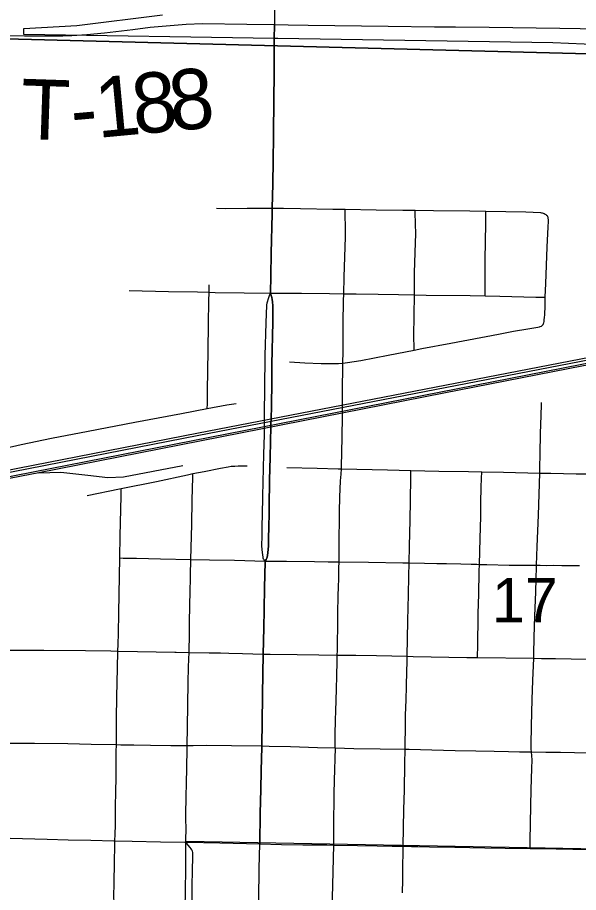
# Model space of a CAD drawing. Extents: x 0 to 34, y 0 to 22.
# Drawn here: x 6.731 to 7.261, y 17.768 to 18.594 of the extents above; entities that cross this region are included whole.
import ezdxf

# ---------------------------------------------------------------- set-up
doc = ezdxf.new("R2010")
doc.units = 0
for name, color, linetype in [('GM_X_City_Street', 7, 'Continuous'), ('GM_X_Corporation', 7, 'Continuous'), ('GM_X_County_Road', 7, 'Continuous'), ('GM_X_Rail_Line', 7, 'Continuous'), ('GM_X_Section_Text', 7, 'Continuous'), ('GM_X_State_Route', 7, 'Continuous'), ('GM_X_Township_Road', 7, 'Continuous'), ('GM_X_Township_Road_Text', 7, 'Continuous'), ('GM_X_US_Route', 7, 'Continuous')]:
    doc.layers.add(name, color=color, linetype=linetype)

msp = doc.modelspace()

# ---------------------------------------------------------------- linework, layer by layer
at = {"layer": 'GM_X_City_Street'}
for points in [[(6.91935, 18.41353), (6.92749, 18.41335), (6.94807, 18.41363), (6.97188, 18.41357)], [(6.97188, 18.41357), (6.97467, 18.41357), (6.98258, 18.41358), (6.99857, 18.41347), (7.02905, 18.41288), (7.04072, 18.41268), (7.0701, 18.4122), (7.09499, 18.41189), (7.10683, 18.41176), (7.12423, 18.41156), (7.15844, 18.4112), (7.17344, 18.41094), (7.21135, 18.4103), (7.22499, 18.40956), (7.2259, 18.4094), (7.22679, 18.40917), (7.2277, 18.40887), (7.22855, 18.40853), (7.2294, 18.40806), (7.23014, 18.40756), (7.23088, 18.40699), (7.23153, 18.40632)], [(7.03117, 17.90465), (7.03141, 17.9182), (7.03168, 17.92982), (7.0319, 17.94059), (7.03212, 17.94843), (7.03256, 17.96109), (7.03286, 17.97126), (7.033, 17.97692), (7.03315, 17.98159), (7.03322, 17.98709), (7.03329, 17.9922), (7.03339, 17.99637), (7.03342, 17.99986), (7.0335, 18.00472), (7.03358, 18.00969), (7.03365, 18.01332), (7.03368, 18.01959), (7.03372, 18.02643), (7.03371, 18.03208), (7.03378, 18.03728), (7.034, 18.04225), (7.03415, 18.04873), (7.03437, 18.05574), (7.03459, 18.06478), (7.03481, 18.07405), (7.03498, 18.08022), (7.03502, 18.08664), (7.03509, 18.09116), (7.03509, 18.0959), (7.03509, 18.10186), (7.03516, 18.10796), (7.03523, 18.11379), (7.0353, 18.11934), (7.03544, 18.12741), (7.03575, 18.1411), (7.0364, 18.15642), (7.03685, 18.16268), (7.03716, 18.16781), (7.03726, 18.16967), (7.03775, 18.19768), (7.03813, 18.21739), (7.03826, 18.22846), (7.03831, 18.23748), (7.03825, 18.24681), (7.03835, 18.26026), (7.03852, 18.26748), (7.03879, 18.27857), (7.03885, 18.28573), (7.0389, 18.29654), (7.03891, 18.30523), (7.0392, 18.32628), (7.03938, 18.33302), (7.03979, 18.34874), (7.04087, 18.38669), (7.04091, 18.39356), (7.04075, 18.40926), (7.04072, 18.41268)], [(7.10586, 18.27985), (7.10581, 18.28154), (7.10548, 18.29304), (7.10603, 18.33189), (7.10607, 18.34144), (7.10627, 18.35263), (7.10723, 18.3812), (7.1073, 18.38928), (7.10688, 18.40925), (7.10683, 18.41176)], [(7.17286, 18.33101), (7.17288, 18.33807), (7.17296, 18.36534), (7.17353, 18.39881), (7.17347, 18.40687), (7.17344, 18.41094)], [(7.22405, 18.3017), (7.22475, 18.30191), (7.22586, 18.30242), (7.22677, 18.30303), (7.22753, 18.30397), (7.22791, 18.30478), (7.22817, 18.30563), (7.22843, 18.30686), (7.22866, 18.30839), (7.22887, 18.31061), (7.22901, 18.31295), (7.22938, 18.32162), (7.22956, 18.32966), (7.22997, 18.34275), (7.23142, 18.37686), (7.23239, 18.39607), (7.23256, 18.40101), (7.2325, 18.4027), (7.23238, 18.4041), (7.23217, 18.40494), (7.23196, 18.40553), (7.23153, 18.40632)], [(6.9106, 18.22466), (6.91065, 18.22922), (6.91076, 18.24168), (6.91146, 18.27906), (6.91177, 18.30464), (6.91203, 18.3258), (6.91221, 18.33441), (6.91236, 18.34148)], [(6.83672, 18.33596), (6.87398, 18.3352), (6.90136, 18.33474), (6.91221, 18.33441), (6.91815, 18.33422), (6.94554, 18.33372), (6.97019, 18.33345)], [(6.97019, 18.33345), (6.98039, 18.33356), (6.99952, 18.33337), (7.02577, 18.33305), (7.03938, 18.33302), (7.05123, 18.333), (7.07171, 18.33253), (7.09096, 18.33217), (7.10603, 18.33189), (7.11703, 18.33168), (7.15864, 18.33129), (7.17286, 18.33101), (7.18657, 18.33074), (7.22071, 18.32988), (7.22956, 18.32966)], [(6.98822, 18.26859), (7.00266, 18.2679), (7.01816, 18.26725), (7.02804, 18.26706), (7.0344, 18.26721), (7.03852, 18.26748), (7.04302, 18.26797), (7.05563, 18.27004), (7.08123, 18.27503), (7.10586, 18.27985), (7.11294, 18.28123), (7.14035, 18.28641), (7.18552, 18.29487), (7.19956, 18.29759), (7.21305, 18.29994), (7.22246, 18.30141), (7.22405, 18.3017)], [(6.71977, 18.18742), (6.73483, 18.19074), (6.76344, 18.19674), (6.7983, 18.20334), (6.84229, 18.21188), (6.88634, 18.2201), (6.9106, 18.22466), (6.92916, 18.22815), (6.93772, 18.22953)], [(7.21658, 17.90088), (7.21624, 17.90352), (7.21615, 17.90743), (7.2166, 17.92534), (7.21727, 17.95015), (7.21778, 17.96812), (7.21863, 17.98909), (7.2188, 17.99377), (7.21904, 18.00848), (7.21937, 18.01929), (7.21971, 18.02873), (7.22059, 18.05182), (7.22092, 18.06416), (7.22096, 18.066), (7.22121, 18.07356), (7.22126, 18.07684), (7.22193, 18.09445), (7.22317, 18.1242), (7.22436, 18.16381), (7.22444, 18.16874), (7.22469, 18.1821), (7.2251, 18.20124), (7.22568, 18.21816), (7.2259, 18.22848), (7.22601, 18.2305)], [(6.79732, 18.14267), (6.82778, 18.14887), (6.8293, 18.14918), (6.8625, 18.15598), (6.89197, 18.16223), (6.89699, 18.16326), (6.90753, 18.16543), (6.9231, 18.16847), (6.93034, 18.1698), (6.93323, 18.17018), (6.93648, 18.17047), (6.93958, 18.17062), (6.94329, 18.1707), (6.94811, 18.17063)], [(6.98573, 18.16892), (7.01431, 18.16832), (7.0342, 18.16789), (7.03716, 18.16781), (7.0808, 18.16673), (7.10264, 18.16629), (7.12925, 18.16575), (7.15722, 18.16528), (7.16954, 18.16502), (7.19015, 18.16459), (7.22436, 18.16381), (7.2349, 18.16361), (7.25884, 18.16324), (7.27466, 18.163)], [(7.09551, 17.8118), (7.09618, 17.84643), (7.09661, 17.8648), (7.09703, 17.88962), (7.09721, 17.90335), (7.09753, 17.92815), (7.09777, 17.93559), (7.09823, 17.94984), (7.09855, 17.96263), (7.09888, 17.97743), (7.09913, 17.98525), (7.09929, 17.99112), (7.09986, 18.0243), (7.10011, 18.03705), (7.10044, 18.04905), (7.10093, 18.06657), (7.1011, 18.07899), (7.10134, 18.09473), (7.10197, 18.11932), (7.10233, 18.13786), (7.10257, 18.15957), (7.10264, 18.16629)], [(6.89161, 17.90672), (6.89185, 17.92416), (6.89265, 17.96632), (6.89291, 17.98087), (6.89313, 17.98818), (6.89335, 17.99466), (6.8937, 18.0126), (6.89393, 18.02375), (6.89422, 18.03784), (6.89453, 18.05351), (6.89462, 18.06341), (6.89488, 18.06959), (6.89512, 18.08011), (6.89518, 18.08223), (6.89589, 18.11539), (6.8964, 18.13829), (6.89691, 18.15992), (6.89699, 18.16326)], [(7.1656, 17.98984), (7.16563, 17.99173), (7.16578, 17.99977), (7.16593, 18.00672), (7.16605, 18.01174), (7.16615, 18.01858), (7.16623, 18.02287), (7.16638, 18.03067), (7.16661, 18.04113), (7.16676, 18.04909), (7.16728, 18.07141), (7.1674, 18.07767), (7.16814, 18.10217), (7.16868, 18.1227), (7.16865, 18.12636), (7.16872, 18.13018), (7.16879, 18.13588), (7.16902, 18.15063), (7.16932, 18.15859), (7.16954, 18.16502)], [(6.82337, 17.81688), (6.82357, 17.82334), (6.82385, 17.83176), (6.82385, 17.83787), (6.82388, 17.84449), (6.82398, 17.85315), (6.82413, 17.85927), (6.82435, 17.86665), (6.82457, 17.87336), (6.82457, 17.88165), (6.82464, 17.8864), (6.82471, 17.89355), (6.8247, 17.90082), (6.82475, 17.90769), (6.82477, 17.91111), (6.82492, 17.91714), (6.82491, 17.92204), (6.82491, 17.92619), (6.82498, 17.93229), (6.82526, 17.95279), (6.82568, 17.97993), (6.82621, 17.99597), (6.82643, 18.00252), (6.82665, 18.01247), (6.82707, 18.03208), (6.82807, 18.08371), (6.82845, 18.10475), (6.82916, 18.14201), (6.8293, 18.14918)], [(6.82807, 18.08371), (6.83127, 18.08366), (6.84371, 18.08343), (6.86641, 18.08291), (6.89518, 18.08223), (6.91272, 18.08196), (6.93629, 18.08159), (6.96507, 18.08087)], [(6.96507, 18.08087), (6.98537, 18.08083), (7.01168, 18.08041), (7.0246, 18.08018), (7.03498, 18.08022), (7.06265, 18.07983), (7.09498, 18.07909), (7.1011, 18.07899), (7.11573, 18.07872), (7.12719, 18.07858), (7.13637, 18.07846), (7.14975, 18.07816), (7.1595, 18.07789), (7.16507, 18.07774), (7.1674, 18.07767), (7.17061, 18.07757), (7.17431, 18.07748), (7.19537, 18.07708), (7.21094, 18.07696), (7.22126, 18.07684), (7.22482, 18.0768), (7.23077, 18.07673), (7.23733, 18.0768), (7.2452, 18.07674), (7.2528, 18.07667), (7.2618, 18.0766)], [(6.72045, 17.90906), (6.73489, 17.90918), (6.74754, 17.90908), (6.77907, 17.90877), (6.80094, 17.90823), (6.82475, 17.90769), (6.82902, 17.90759), (6.84123, 17.90738), (6.85711, 17.90706), (6.87631, 17.90674), (6.89161, 17.90672)], [(6.89593, 17.74841), (6.89636, 17.77391), (6.89673, 17.78943), (6.89692, 17.80126), (6.89696, 17.80495), (6.89683, 17.80606), (6.89655, 17.80718), (6.89604, 17.80839), (6.89538, 17.80946), (6.89447, 17.81063), (6.89256, 17.81291), (6.89027, 17.81555), (6.8903, 17.81734), (6.89049, 17.82874), (6.89048, 17.8372), (6.89046, 17.84365), (6.89075, 17.85661), (6.89104, 17.87342), (6.89115, 17.88315), (6.8916, 17.90621)], [(6.89161, 17.90672), (6.89729, 17.90687), (6.91017, 17.9071), (6.93341, 17.90695), (6.96194, 17.90641), (6.96911, 17.90626), (6.98921, 17.90583), (7.01474, 17.90507), (7.03117, 17.90465), (7.03037, 17.87375), (7.03009, 17.86146), (7.0298, 17.83019), (7.02973, 17.82387), (7.02961, 17.81294), (7.02781, 17.73798)], [(7.03117, 17.90465), (7.04901, 17.90415), (7.07381, 17.90376), (7.09721, 17.90335), (7.10116, 17.90328), (7.12242, 17.90272), (7.14466, 17.90222), (7.16394, 17.90176), (7.18137, 17.90143), (7.1948, 17.90111), (7.20534, 17.90101), (7.21275, 17.90088), (7.21658, 17.90088), (7.23022, 17.90071), (7.24386, 17.90048), (7.25707, 17.90017), (7.26851, 17.89995)], [(7.21524, 17.80971), (7.21537, 17.81684), (7.21601, 17.84985), (7.21633, 17.86531), (7.21693, 17.88506), (7.21718, 17.89331), (7.21701, 17.89697), (7.21658, 17.90088)], [(6.82262, 17.75329), (6.82253, 17.76991), (6.82269, 17.77167), (6.82275, 17.77351), (6.82273, 17.7772), (6.82303, 17.79645), (6.82311, 17.8014), (6.82324, 17.80775), (6.82337, 17.81688)], [(6.9584, 17.72485), (6.94653, 17.72534), (6.91238, 17.72615), (6.90572, 17.72626), (6.90456, 17.72629), (6.90276, 17.72632), (6.88933, 17.72666), (6.88954, 17.73522), (6.88963, 17.74396), (6.88973, 17.75688), (6.89001, 17.76584), (6.89017, 17.7703), (6.89015, 17.77523), (6.89025, 17.78517), (6.8902, 17.78691), (6.89023, 17.79105), (6.89032, 17.79766), (6.89037, 17.80341), (6.89027, 17.81555)], [(7.0948, 17.76781), (7.09504, 17.78015), (7.09508, 17.78381), (7.0951, 17.78744), (7.09551, 17.8118)]]:
    msp.add_lwpolyline(points, dxfattribs=at)
at = {"layer": 'GM_X_Corporation'}
for points in [[(6.74861, 19.58646), (7.75042, 19.56547), (7.73457, 18.54715), (6.72002, 18.57343), (6.74716, 19.57625)], [(6.72002, 18.57343), (7.73457, 18.54715), (7.70158, 17.53728), (6.70042, 17.56893)]]:
    msp.add_lwpolyline(points, close=True, dxfattribs=at)
msp.add_lwpolyline([(7.34036, 18.56533), (7.23673, 18.56947), (6.97708, 18.57378), (6.97371, 18.57386), (6.73747, 18.5774), (6.73755, 18.58309), (6.78734, 18.58599), (6.86833, 18.59597)], dxfattribs=at)
at = {"layer": 'GM_X_County_Road'}
msp.add_line((7.1656, 17.98984), (7.21863, 17.98909), dxfattribs=at)
for points in [[(6.71521, 17.99663), (6.75634, 17.99667), (6.79556, 17.99651), (6.81962, 17.99601), (6.82621, 17.99597)], [(6.82621, 17.99597), (6.84467, 17.99561), (6.88008, 17.99485), (6.88132, 17.99483), (6.89335, 17.99466)], [(6.89335, 17.99466), (6.91247, 17.99432), (6.91822, 17.99421)], [(6.91822, 17.99421), (6.92301, 17.99412), (6.9308, 17.99398), (6.94389, 17.99378), (6.96335, 17.99314)], [(6.96335, 17.99314), (6.96986, 17.99304), (6.99534, 17.99264), (7.01585, 17.9924), (7.03329, 17.9922)], [(7.03329, 17.9922), (7.05064, 17.99199), (7.07043, 17.99169), (7.09929, 17.99112)], [(7.09929, 17.99112), (7.10474, 17.99095), (7.15544, 17.98998), (7.1656, 17.98984)], [(7.21863, 17.98909), (7.22604, 17.98901), (7.23936, 17.98881), (7.28382, 17.98805)]]:
    msp.add_lwpolyline(points, dxfattribs=at)
at = {"layer": 'GM_X_Rail_Line'}
for p, q in [((6.67145, 18.1505), (8.00771, 18.41211)), ((6.89051, 17.81647), (7.41313, 17.80694))]:
    msp.add_line(p, q, dxfattribs=at)
for points in [[(2.1, 17.25784), (2.18393, 17.27433), (2.73729, 17.38072), (3.32149, 17.49791), (3.96117, 17.62281), (4.55539, 17.74), (5.15654, 17.85642), (5.77541, 17.979), (6.33417, 18.09079), (6.90219, 18.20181), (7.3492, 18.28816), (7.42386, 18.30272), (8.00923, 18.41684), (8.46231, 18.50822), (8.9, 18.59581)], [(2.1, 17.25547), (2.18438, 17.27205), (2.73774, 17.37844), (3.32194, 17.49563), (3.96162, 17.62053), (4.55584, 17.73772), (5.15699, 17.85414), (5.77586, 17.97672), (6.33462, 18.08851), (6.90263, 18.19953), (7.34964, 18.28588), (7.42431, 18.30044), (8.00968, 18.41456), (8.46244, 18.50563), (8.9, 18.59339)], [(7.31039, 18.27271), (7.30702, 18.2722), (7.2655, 18.26481), (7.13398, 18.23932), (6.75163, 18.16404)], [(6.75163, 18.16404), (6.77238, 18.16468), (6.79769, 18.16171), (6.81671, 18.15961), (6.83136, 18.1602), (6.88753, 18.17092)], [(6.75163, 18.16404), (6.7353, 18.16082), (6.709, 18.15589), (6.67145, 18.1505)]]:
    msp.add_lwpolyline(points, dxfattribs=at)
at = {"layer": 'GM_X_State_Route'}
for p, q in [((6.97396, 18.587), (6.97382, 18.57295)), ((7.02352, 17.81307), (7.02961, 17.81294)), ((7.09551, 17.8118), (7.10338, 17.81169))]:
    msp.add_line(p, q, dxfattribs=at)
for points in [[(6.97624, 18.74097), (6.9756, 18.71607), (6.97459, 18.67524), (6.97395, 18.64059), (6.97362, 18.61964), (6.97396, 18.587)], [(6.97382, 18.57295), (6.97383, 18.5657), (6.97384, 18.55828), (6.97377, 18.54797), (6.97368, 18.54156)], [(6.97368, 18.54156), (6.97345, 18.51494), (6.9732, 18.48453)], [(6.9732, 18.48453), (6.97318, 18.48267), (6.97265, 18.45723), (6.97238, 18.43769)], [(6.97238, 18.43769), (6.97237, 18.43672), (6.97188, 18.41357)], [(6.97188, 18.41357), (6.97176, 18.40837), (6.97086, 18.37111), (6.97054, 18.34973), (6.97019, 18.33345)], [(6.97019, 18.33345), (6.97082, 18.33132), (6.97139, 18.32928), (6.97176, 18.32747), (6.97211, 18.32521), (6.97249, 18.32163), (6.97239, 18.3066), (6.97151, 18.26626), (6.9714, 18.25134), (6.97108, 18.22527), (6.9707, 18.20789), (6.96978, 18.17871), (6.96939, 18.15696), (6.96905, 18.13213), (6.96887, 18.12221), (6.96873, 18.11664), (6.96843, 18.09858), (6.96833, 18.09518), (6.96817, 18.09185), (6.96782, 18.08897), (6.96737, 18.0861), (6.96707, 18.08458), (6.96686, 18.08357), (6.96659, 18.08287), (6.96624, 18.08226), (6.96507, 18.08087)], [(6.96507, 18.08087), (6.96476, 18.06713), (6.96464, 18.05609), (6.96413, 18.03496), (6.96383, 18.01775), (6.96335, 17.99314)], [(6.96335, 17.99314), (6.96331, 17.9913), (6.96312, 17.9759), (6.96194, 17.90641)], [(6.96194, 17.90641), (6.96192, 17.90512), (6.96156, 17.88336), (6.96119, 17.86541), (6.96054, 17.84309), (6.9601, 17.81394)], [(6.61705, 17.82221), (6.65994, 17.8212), (6.69163, 17.82025), (6.71069, 17.81967), (6.72442, 17.81931), (6.75957, 17.8185), (6.77916, 17.81795), (6.80081, 17.81743), (6.82234, 17.81691)], [(6.82234, 17.81691), (6.82337, 17.81688), (6.8397, 17.8165), (6.86655, 17.81596), (6.88924, 17.81557), (6.89027, 17.81555), (6.89127, 17.81553)], [(6.89127, 17.81553), (6.92232, 17.81498), (6.9601, 17.81394)], [(6.9584, 17.72485), (6.95912, 17.76148), (6.95961, 17.79068), (6.9601, 17.81394)], [(6.9601, 17.81394), (6.98058, 17.81361), (7.00072, 17.8133), (7.01946, 17.81316), (7.02352, 17.81307)], [(7.02961, 17.81294), (7.05244, 17.81245), (7.07102, 17.81217), (7.08508, 17.81189), (7.09551, 17.8118)], [(7.10338, 17.81169), (7.10927, 17.81161), (7.12019, 17.81133), (7.14437, 17.81095), (7.17255, 17.81038), (7.19185, 17.81009), (7.21524, 17.80971)], [(7.21524, 17.80971), (7.21625, 17.80969), (7.23971, 17.80929), (7.25548, 17.80899), (7.27136, 17.80869), (7.27842, 17.80855)]]:
    msp.add_lwpolyline(points, dxfattribs=at)
at = {"layer": 'GM_X_Township_Road'}
for points in [[(6.77317, 18.57633), (6.77414, 18.57636), (6.78281, 18.57664), (6.79703, 18.5775), (6.81369, 18.57904), (6.84016, 18.58225), (6.8568, 18.58436), (6.89061, 18.58738), (6.90609, 18.58788), (6.94778, 18.58725), (6.97396, 18.587)], [(6.97396, 18.587), (6.98691, 18.58654), (7.00567, 18.58626), (7.08132, 18.58527), (7.12511, 18.58485), (7.14493, 18.5846), (7.17669, 18.58443), (7.24328, 18.5835), (7.30115, 18.58243), (7.34195, 18.58155), (7.38636, 18.58059), (7.40812, 18.57984), (7.42128, 18.57924)], [(6.48126, 18.57829), (6.50545, 18.57826), (6.53154, 18.57807), (6.58371, 18.57774), (6.63837, 18.57748), (6.65825, 18.57718), (6.70669, 18.57695), (6.73796, 18.57638)], [(6.73796, 18.57638), (6.76547, 18.57607), (6.77317, 18.57633)]]:
    msp.add_lwpolyline(points, dxfattribs=at)
at = {"layer": 'GM_X_US_Route'}
msp.add_line((6.97382, 18.57295), (6.97396, 18.587), dxfattribs=at)
for points in [[(6.97396, 18.587), (6.98691, 18.58654), (7.00567, 18.58626), (7.08132, 18.58527), (7.12511, 18.58485), (7.14493, 18.5846), (7.17669, 18.58443), (7.24328, 18.5835), (7.30115, 18.58243), (7.34195, 18.58155), (7.38636, 18.58059), (7.40812, 18.57984), (7.42128, 18.57924)], [(6.97368, 18.54156), (6.97377, 18.54797), (6.97384, 18.55828), (6.97383, 18.5657), (6.97382, 18.57295)], [(6.9732, 18.48453), (6.97345, 18.51494), (6.97368, 18.54156)], [(6.97238, 18.43769), (6.97265, 18.45723), (6.97318, 18.48267), (6.9732, 18.48453)], [(6.97188, 18.41357), (6.97237, 18.43672), (6.97238, 18.43769)], [(6.97019, 18.33345), (6.97054, 18.34973), (6.97086, 18.37111), (6.97176, 18.40837), (6.97188, 18.41357)], [(6.96507, 18.08087), (6.96412, 18.08205), (6.96372, 18.08274), (6.96345, 18.08349), (6.96322, 18.08458), (6.96271, 18.08881), (6.96239, 18.09178), (6.96217, 18.09507), (6.96228, 18.10459), (6.96228, 18.10641), (6.96234, 18.10888), (6.96231, 18.11007), (6.96241, 18.11432), (6.96259, 18.12418), (6.963, 18.14217), (6.96402, 18.18153), (6.96456, 18.19996), (6.96472, 18.22049), (6.96503, 18.24292), (6.96536, 18.27456), (6.96603, 18.30562), (6.96666, 18.32215), (6.96703, 18.32423), (6.9673, 18.32534), (6.9683, 18.32854), (6.96937, 18.33125), (6.97019, 18.33345)], [(6.96507, 18.08087), (6.96624, 18.08226), (6.96659, 18.08287), (6.96686, 18.08357), (6.96707, 18.08458), (6.96737, 18.0861), (6.96782, 18.08897), (6.96817, 18.09185), (6.96833, 18.09518), (6.96843, 18.09858), (6.96873, 18.11664), (6.96887, 18.12221), (6.96905, 18.13213), (6.96939, 18.15696), (6.96978, 18.17871), (6.9707, 18.20789), (6.97108, 18.22527), (6.9714, 18.25134), (6.97151, 18.26626), (6.97239, 18.3066), (6.97249, 18.32163), (6.97211, 18.32521), (6.97176, 18.32747), (6.97139, 18.32928), (6.97082, 18.33132), (6.97019, 18.33345)], [(6.96335, 17.99314), (6.96383, 18.01775), (6.96413, 18.03496), (6.96464, 18.05609), (6.96476, 18.06713), (6.96507, 18.08087)], [(6.96194, 17.90641), (6.96312, 17.9759), (6.96331, 17.9913), (6.96335, 17.99314)], [(6.9601, 17.81394), (6.96054, 17.84309), (6.96119, 17.86541), (6.96156, 17.88336), (6.96192, 17.90512), (6.96194, 17.90641)], [(6.9584, 17.72485), (6.95912, 17.76148), (6.95961, 17.79068), (6.9601, 17.81394)]]:
    msp.add_lwpolyline(points, dxfattribs=at)

# ---------------------------------------------------------------- texts
at = {"layer": 'GM_X_Section_Text'}
msp.add_text('17', height=0.041856, rotation=0.00001, dxfattribs=at).set_placement((7.17914, 18.02302))
at = {"layer": 'GM_X_Township_Road_Text'}
for s, rotation, p in [('8', 5.00479, (6.87685, 18.48643)), ('1', 5.34494, (6.80721, 18.47988)), ('8', 5.39662, (6.84211, 18.48315)), ('T', 358.11612, (6.73368, 18.479)), ('-', 5.03152, (6.78363, 18.4778))]:
    msp.add_text(s, height=0.05682, rotation=rotation, dxfattribs=at).set_placement(p)

doc.saveas('drawing.dxf')
